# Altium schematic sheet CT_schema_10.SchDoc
size 274 x 160 mm
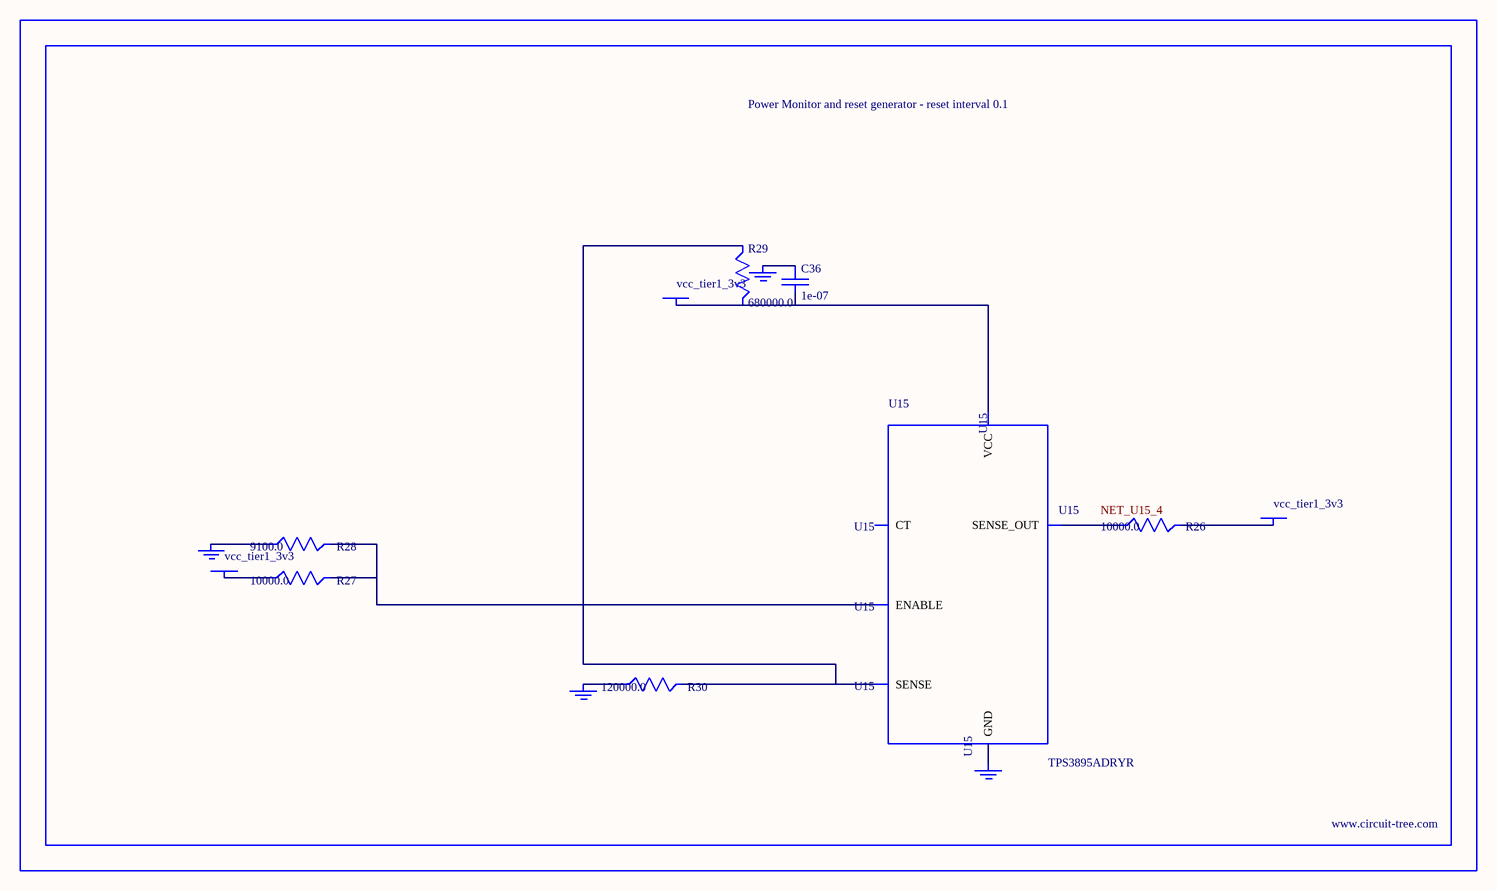
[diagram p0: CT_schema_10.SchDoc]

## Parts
BORDER9  (no value)
C36  1e-07  [C0402]
GND_INSTANCE_9_0  (no value)
GND_INSTANCE_9_1  (no value)
GND_INSTANCE_9_2  (no value)
GND_INSTANCE_9_3  (no value)
POWER_INSTANCE_9_0  vcc_tier1_3v3
POWER_INSTANCE_9_1  vcc_tier1_3v3
POWER_INSTANCE_9_2  vcc_tier1_3v3
R26  10000.0  [R0603]
R27  10000.0  [R0603]
R28  9100.0  [R0603]
R29  680000.0  [R0603]
R30  120000.0  [R0603]
U15  TPS3895ADRYR  [SON-6]

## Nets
NetC36_1: C36.1 GND_INSTANCE_9_2.0(GND)
NetC36_2: C36.2 POWER_INSTANCE_9_2.0(PWR) R29.2 U15.6(VCC)
NetGND_INSTANCE_9_0_0: GND_INSTANCE_9_0.0(GND) R28.1
NetGND_INSTANCE_9_1_0: GND_INSTANCE_9_1.0(GND) R30.1
NetGND_INSTANCE_9_3_0: GND_INSTANCE_9_3.0(GND) U15.2(GND)
NetPOWER_INSTANCE_9_0_0: POWER_INSTANCE_9_0.0(PWR) R27.1
NetPOWER_INSTANCE_9_1_0: POWER_INSTANCE_9_1.0(PWR) R26.2
NetR26_1: R26.1 U15.4(SENSE_OUT)
NetR27_2: R27.2 R28.2 U15.1(ENABLE)
NetR29_1: R29.1 R30.2 U15.3(SENSE)

Not connected (* = marked no-connect by the designer): U15 5(CT)

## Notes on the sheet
- Labels drawn without touching a wire or pin: NET_U15_4

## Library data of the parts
BORDER9 = BORDER_PAGE9
C36 = C0402C104K3RACTU
GND_INSTANCE_9_0-GND_INSTANCE_9_3 = GND
POWER_INSTANCE_9_0-POWER_INSTANCE_9_2 = PWR
R26 R27 = RC0603JR-0710KL
R28 = RC0603JR-079K1L
R29 = RC0603JR-07680KL
R30 = RC0603JR-07120KL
